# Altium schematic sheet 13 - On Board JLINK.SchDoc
size B; CompanyName: Microchip Technology Inc.; Organization: Microchip Technology; Address1: 2355 West Chandler Blvd.; Address2: Chandler, AZ  85224; Address4: USA; DocumentNumber: 13; SheetNumber: 13; SheetTotal: 13; SheetTitle: On Board JLINK
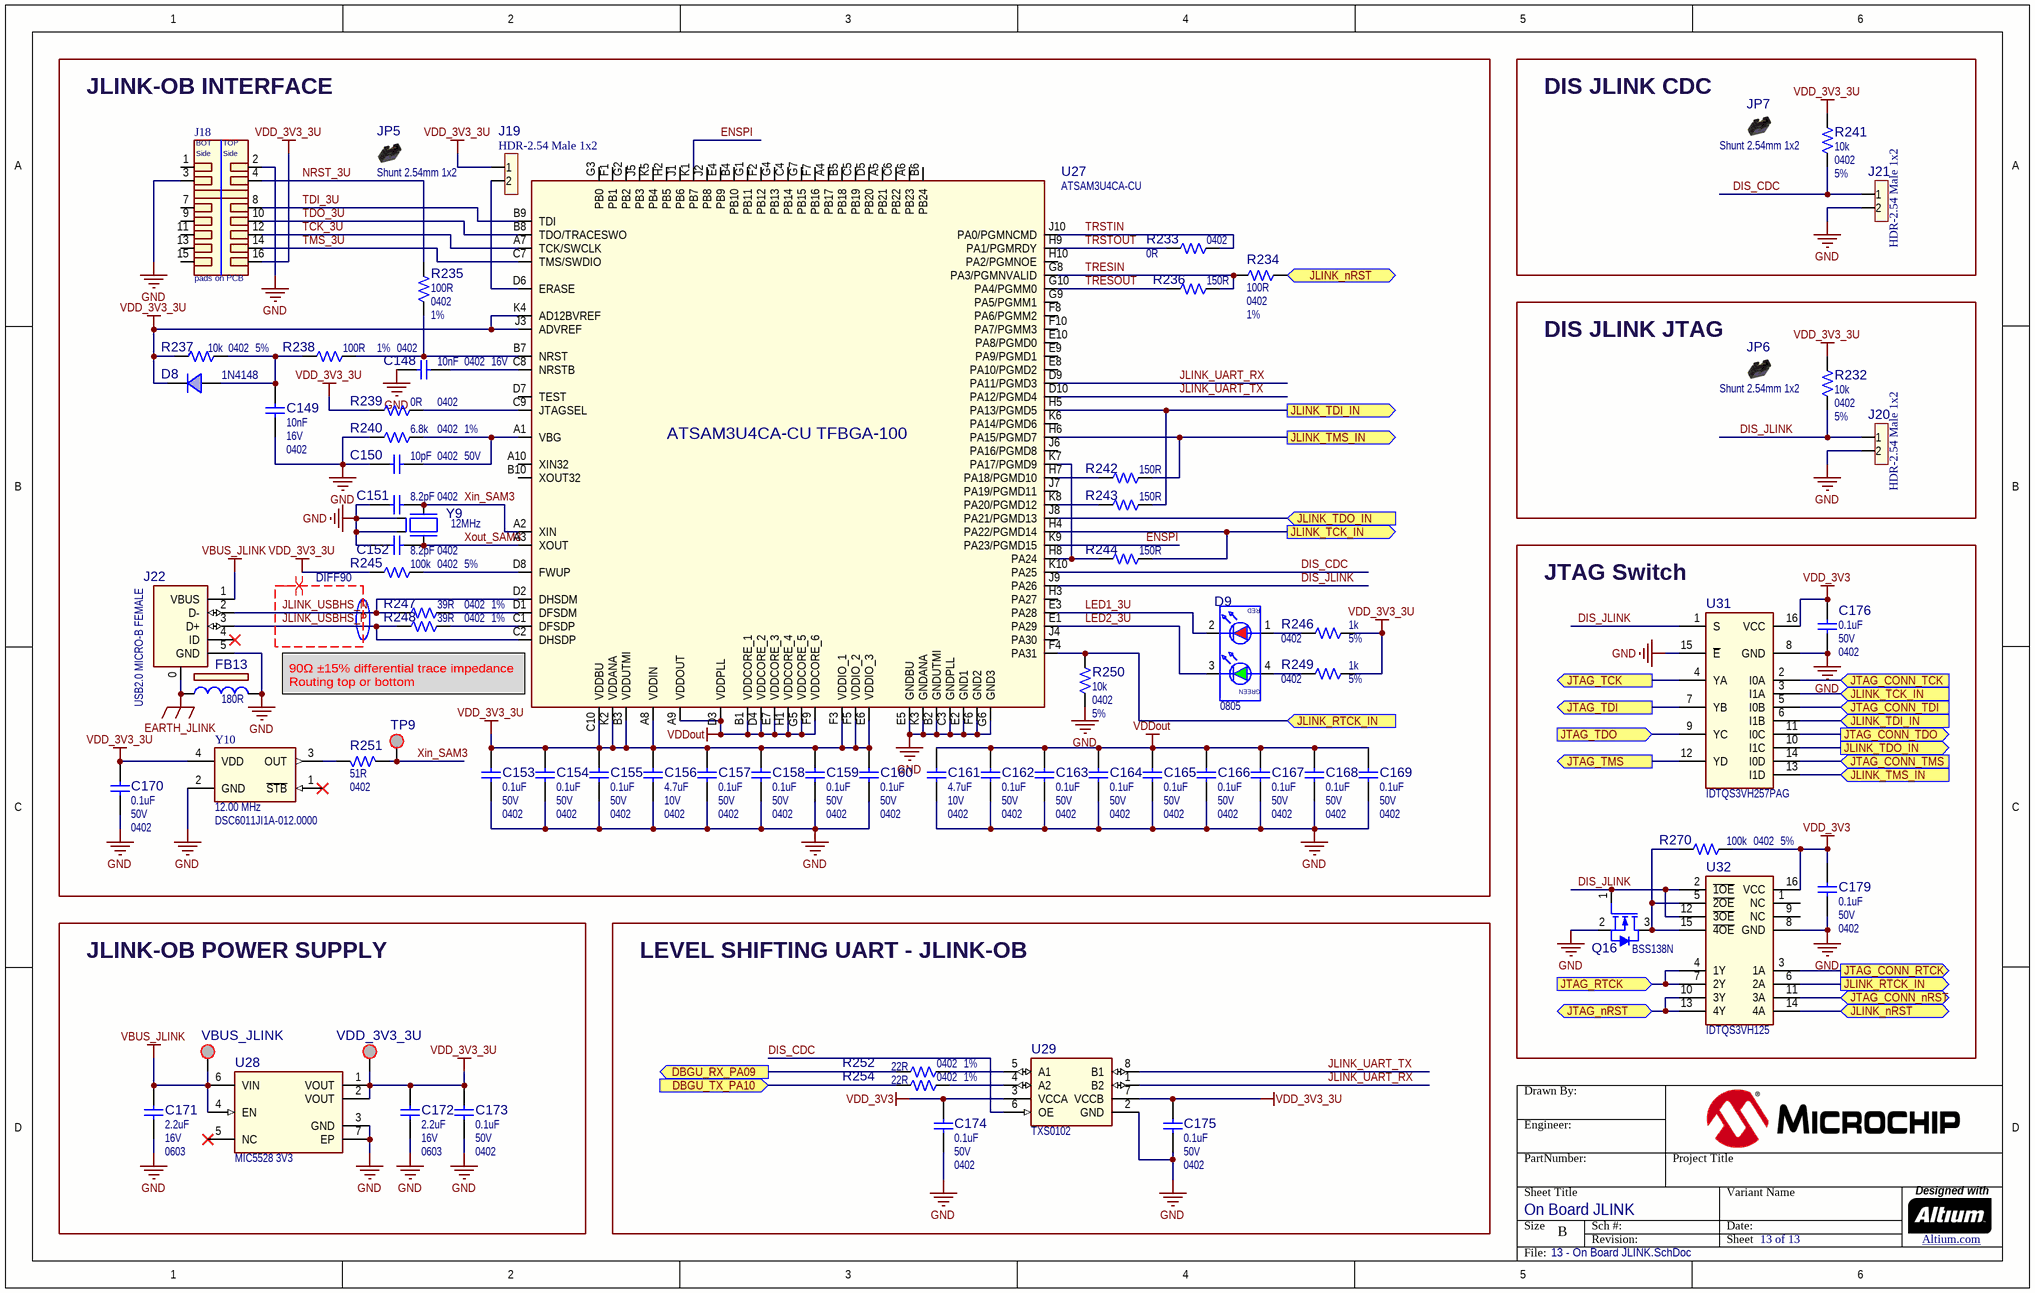
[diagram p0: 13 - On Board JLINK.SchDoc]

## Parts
?  (no value)  (graphical)
C148  value 10nF  Voltage: 16V  Package: 0402  [CAP_C_0402]  (hidden comment: Capacitor NP)
C149  value 10nF  Voltage: 16V  Package: 0402  [CAP_C_0402]  (hidden comment: Capacitor NP)
C150  value 10pF  Voltage: 50V  Package: 0402  [CAP_C_0402]  (hidden comment: Capacitor NP)
C151  value 8.2pF  Package: 0402  [CAP_C_0402]  (hidden comment: Capacitor NP)
C152  value 8.2pF  Package: 0402  [CAP_C_0402]  (hidden comment: Capacitor NP)
C153  value 0.1uF  Voltage: 50V  Package: 0402  [CAP_C_0402]  (hidden comment: Capacitor NP)
C154  value 0.1uF  Voltage: 50V  Package: 0402  [CAP_C_0402]  (hidden comment: Capacitor NP)
C155  value 0.1uF  Voltage: 50V  Package: 0402  [CAP_C_0402]  (hidden comment: Capacitor NP)
C156  value 4.7uF  Voltage: 10V  Package: 0402  [CAP_C_0402]  (hidden comment: Capacitor NP)
C157  value 0.1uF  Voltage: 50V  Package: 0402  [CAP_C_0402]  (hidden comment: Capacitor NP)
C158  value 0.1uF  Voltage: 50V  Package: 0402  [CAP_C_0402]  (hidden comment: Capacitor NP)
C159  value 0.1uF  Voltage: 50V  Package: 0402  [CAP_C_0402]  (hidden comment: Capacitor NP)
C160  value 0.1uF  Voltage: 50V  Package: 0402  [CAP_C_0402]  (hidden comment: Capacitor NP)
C161  value 4.7uF  Voltage: 10V  Package: 0402  [CAP_C_0402]  (hidden comment: Capacitor NP)
C162  value 0.1uF  Voltage: 50V  Package: 0402  [CAP_C_0402]  (hidden comment: Capacitor NP)
C163  value 0.1uF  Voltage: 50V  Package: 0402  [CAP_C_0402]  (hidden comment: Capacitor NP)
C164  value 0.1uF  Voltage: 50V  Package: 0402  [CAP_C_0402]  (hidden comment: Capacitor NP)
C165  value 0.1uF  Voltage: 50V  Package: 0402  [CAP_C_0402]  (hidden comment: Capacitor NP)
C166  value 0.1uF  Voltage: 50V  Package: 0402  [CAP_C_0402]  (hidden comment: Capacitor NP)
C167  value 0.1uF  Voltage: 50V  Package: 0402  [CAP_C_0402]  (hidden comment: Capacitor NP)
C168  value 0.1uF  Voltage: 50V  Package: 0402  [CAP_C_0402]  (hidden comment: Capacitor NP)
C169  value 0.1uF  Voltage: 50V  Package: 0402  [CAP_C_0402]  (hidden comment: Capacitor NP)
C170  value 0.1uF  Voltage: 50V  Package: 0402  [CAP_C_0402]  (hidden comment: Capacitor NP)
C171  value 2.2uF  Voltage: 16V  Package: 0603  [CAP_C_0603]  (hidden comment: Capacitor NP)
C172  value 2.2uF  Voltage: 16V  Package: 0603  [CAP_C_0603]  (hidden comment: Capacitor NP)
C173  value 0.1uF  Voltage: 50V  Package: 0402  [CAP_C_0402]  (hidden comment: Capacitor NP)
C174  value 0.1uF  Voltage: 50V  Package: 0402  [CAP_C_0402]  (hidden comment: Capacitor NP)
C175  value 0.1uF  Voltage: 50V  Package: 0402  [CAP_C_0402]  (hidden comment: Capacitor NP)
C176  value 0.1uF  Voltage: 50V  Package: 0402  [CAP_C_0402]  (hidden comment: Capacitor NP)
C179  value 0.1uF  Voltage: 50V  Package: 0402  [CAP_C_0402]  (hidden comment: Capacitor NP)
D8  value 1N4148  [SOD-323]  (hidden comment: Diode Single)
D9  Package: 0805  [LED_DUAL_SMD_2x1.25mm]  (hidden comment: LED DUAL 4 pin)
FB13  value 180R  [IND_C_0603]  (hidden comment: Ferrite Bead)
J18  pads on PCB  [CON_EDGE-CARD_PCB_RA_MEC1-108-02-F-D-RA1-SL]  (no BOM)
J19  value HDR-2.54 Male 1x2  [HDR_M_2.54_1x2]  (hidden comment: Header 1x2)
J20  value HDR-2.54 Male 1x2  [HDR_M_2.54_1x2]  (hidden comment: Header 1x2)
J21  value HDR-2.54 Male 1x2  [HDR_M_2.54_1x2]  (hidden comment: Header 1x2)
J22  value USB2.0 MICRO-B FEMALE  [CON_USB_Micro-AB_SMD_TH_RA_FCI_10118194-0001LF]  (hidden comment: CON USB2.0 Mini_Micro)
JP5  value Shunt 2.54mm 1x2  [Jumper_Mechanical]  (hidden comment: Jumper Mechanical)  (mechanical)
JP6  value Shunt 2.54mm 1x2  [Jumper_Mechanical]  (hidden comment: Jumper Mechanical)  (mechanical)
JP7  value Shunt 2.54mm 1x2  [Jumper_Mechanical]  (hidden comment: Jumper Mechanical)  (mechanical)
Q16  value BSS138N  [SOT-23-3]  (hidden comment: Transistor MOS-N GSD)
R232  value 10k  Package: 0402  Tolerance: 5%  [RES_C_0402]  (hidden comment: Resistor)
R233  value 0R  Package: 0402  [RES_C_0402]  (hidden comment: Resistor)
R234  value 100R  Package: 0402  Tolerance: 1%  [RES_C_0402]  (hidden comment: Resistor)
R235  value 100R  Package: 0402  Tolerance: 1%  [RES_C_0402]  (hidden comment: Resistor)
R236  value 150R  [RES_C_0402]  (hidden comment: Resistor)
R237  value 10k  Package: 0402  Tolerance: 5%  [RES_C_0402]  (hidden comment: Resistor)
R238  value 100R  Package: 0402  Tolerance: 1%  [RES_C_0402]  (hidden comment: Resistor)
R239  value 0R  Package: 0402  [RES_C_0402]  (hidden comment: Resistor)
R240  value 6.8k  Package: 0402  Tolerance: 1%  [RES_C_0402]  (hidden comment: Resistor)
R241  value 10k  Package: 0402  Tolerance: 5%  [RES_C_0402]  (hidden comment: Resistor)
R242  value 150R  [RES_C_0402]  (hidden comment: Resistor)
R243  value 150R  [RES_C_0402]  (hidden comment: Resistor)
R244  value 150R  [RES_C_0402]  (hidden comment: Resistor)
R245  value 100k  Package: 0402  Tolerance: 5%  [RES_C_0402]  (hidden comment: Resistor)
R246  value 1k  Package: 0402  Tolerance: 5%  [RES_C_0402]  (hidden comment: Resistor)
R247  value 39R  Package: 0402  Tolerance: 1%  [RES_C_0402]  (hidden comment: Resistor)
R248  value 39R  Package: 0402  Tolerance: 1%  [RES_C_0402]  (hidden comment: Resistor)
R249  value 1k  Package: 0402  Tolerance: 5%  [RES_C_0402]  (hidden comment: Resistor)
R250  value 10k  Package: 0402  Tolerance: 5%  [RES_C_0402]  (hidden comment: Resistor)
R251  value 51R  Package: 0402  [RES_C_0402]  (hidden comment: Resistor)
R252  value 22R  Package: 0402  Tolerance: 1%  [RES_C_0402]  (hidden comment: Resistor)
R254  value 22R  Package: 0402  Tolerance: 1%  [RES_C_0402]  (hidden comment: Resistor)
R270  value 100k  Package: 0402  Tolerance: 5%  [RES_C_0402]  (hidden comment: Resistor)
TP9  SMD Test Point  [TP_1x1_SMD]  (value not drawn)  (no BOM)
U27  ATSAM3U4CA-CU TFBGA-100  value ATSAM3U4CA-CU  [TFBGA-100_P0.8_9x9x1.1]
U28  value MIC5528 3V3  [DFN-6_1.2x1.2]  (hidden comment: MIC5528MT DFN-6)
U29  TXS0102  [US-8]
U31  value IDTQS3VH257PAG  [TSSOP-16]  (hidden comment: IDTQS3VH257 TSSOP-16)
U32  value IDTQS3VH125  [QSOP-16]  (hidden comment: IDTQS3VH125 SSOP-16)
VBUS_JLINK  SMD Test Point  [TP_1x1_SMD]  (value not drawn)  (no BOM)
VDD_3V3_3U  SMD Test Point  [TP_1x1_SMD]  (value not drawn)  (no BOM)
Y9  value 12MHz  [CRYSTAL_L7.5W5.2H1.4]  (hidden comment: Crystal 4 Pins)
Y10  value 12.00 MHz  Manufacturer Part Number 1: DSC6011JI1A-012.0000  [OSCILLATOR_DSC60000L2.5W2.0H0.89]  (hidden comment: OSCILLATOR DSC60XX)

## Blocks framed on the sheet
JLINK-OB INTERFACE: C148-C170 D8 D9 FB13 J18 J19 J22 JP5 R233-R240 R242-R251 TP9 U27 Y9 Y10
DIS JLINK CDC: J21 JP7 R241
DIS JLINK JTAG: J20 JP6 R232
JTAG Switch: C176 C179 Q16 R270 U31 U32
JLINK-OB POWER SUPPLY: C171-C173 U28 VBUS_JLINK VDD_3V3_3U
LEVEL SHIFTING UART - JLINK-OB: C174 C175 R252 R254 U29

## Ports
DBGU_RX_PA09 (out), DBGU_TX_PA10 (in), JLINK_nRST (bidir), JLINK_RTCK_IN (in), JLINK_RTCK_IN (out), JLINK_TCK_IN (in), JLINK_TCK_IN (out), JLINK_TDI_IN (in), JLINK_TDI_IN (out), JLINK_TDO_IN (in), JLINK_TDO_IN (out), JLINK_TMS_IN (in), JLINK_TMS_IN (out), JTAG_CONN_nRST (bidir), JTAG_CONN_RTCK (out), JTAG_CONN_TCK (in), JTAG_CONN_TDI (in), JTAG_CONN_TDO (out), JTAG_CONN_TMS (in), JTAG_nRST (bidir), JTAG_RTCK (in), JTAG_TCK (out), JTAG_TDI (out), JTAG_TDO (in), JTAG_TMS (out)

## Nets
EARTH_JLINK: FB13.1 J22.0(SHLD)
GND: C148.1 C149.1 C150.2 C151.2 C152.2 C153.2 C154.1 C155.2 C156.1 C157.1 C158.1 C159.1 C160.1 C161.1 C162.1 C163.2 C164.2 C165.2 C166.2 C167.2 C168.2 C169.1 C170.1 C171.2 C172.1 C173.1 C174.1 C175.1 C176.2 C179.2 FB13.2 J18.2 J18.3 J20.2 J21.2 J22.5(GND) Q16.2(S) R240.1 R250.2 U27.B2(GNDUTMI) U27.C3(GNDPLL) U27.E2(GND1) U27.E5(GNDBU) U27.F6(GND2) U27.G6(GND3) U27.K3(GNDANA) U28.3(GND) U28.7(EP) U29.2(GND) U31.8(GND) U31.15(~{E}) U32.8(GND) Y9.2(GND) Y9.4(GND) Y10.2(GND)
VBUS_JLINK: C171.1 J22.1(VBUS) U28.4(EN) U28.6(VIN) VBUS_JLINK.1
VDD_3V3: C174.2 C176.1 C179.1 R270.1 U29.3(VCCA) U31.16(VCC) U32.16(VCC)
VDD_3V3_3U: C153.1 C154.2 C155.1 C156.2 C157.2 C158.2 C159.2 C160.2 C170.2 C172.2 C173.2 C175.2 D8.2(K) J18.16 J19.1 R232.1 R237.1 R239.1 R241.1 R245.1 R246.1 R249.1 U27.A8(VDDIN) U27.B3(VDDUTMI) U27.C10(VDDBU) U27.E6(VDDIO_3) U27.F3(VDDIO_1) U27.F5(VDDIO_2) U27.J3(ADVREF) U27.K2(VDDANA) U27.K4(AD12BVREF) U28.1(VOUT) U28.2(VOUT) U29.7(VCCB) VDD_3V3_3U.1 Y10.4(VDD)
VDDout: C161.2 C162.2 C163.1 C164.1 C165.1 C166.1 C167.1 C168.1 C169.2 U27.A9(VDDOUT) U27.B1(VDDCORE_1) U27.D3(VDDPLL) U27.D4(VDDCORE_2) U27.E7(VDDCORE_3) U27.F9(VDDCORE_6) U27.G5(VDDCORE_5) U27.H1(VDDCORE_4)
DBGU_RX_PA09: R252.1 ; port DBGU_RX_PA09
DBGU_TX_PA10: R254.1 ; port DBGU_TX_PA10
DIS_CDC: J21.1 R241.2 U27.K10(PA25) U29.6(OE)
DIS_JLINK: J20.1 Q16.1(G) R232.2 U27.J9(PA26) U31.1(S) U32.2(~{1OE}) U32.12(~{3OE})
ENSPI: U27.K1(PB7) U27.K9(PA23/PGMD15)
JLINK_nRST: R234.2 U32.14(4A) ; port JLINK_nRST
JLINK_RTCK_IN: R250.1 U27.F4(PA31) U32.6(2A) ; port JLINK_RTCK_IN
JLINK_TCK_IN: R244.2 U27.H4(PA22/PGMD14) U31.3(I1A) ; port JLINK_TCK_IN
JLINK_TDI_IN: R243.2 U27.H5(PA13/PGMD5) U31.6(I1B) ; port JLINK_TDI_IN
JLINK_TDO_IN: U27.J8(PA21/PGMD13) U31.10(I1C) ; port JLINK_TDO_IN
JLINK_TMS_IN: R242.2 U27.H6(PA15/PGMD7) U31.13(I1D) ; port JLINK_TMS_IN
JLINK_UART_RX: U27.D9(PA11/PGMD3) U29.1(B2)
JLINK_UART_TX: U27.D10(PA12/PGMD4) U29.8(B1)
JLINK_USBHS_N: J22.2(D-) R247.1 U27.D2(DHSDM)
JLINK_USBHS_P: J22.3(D+) R248.1 U27.C2(DHSDP)
JTAG_CONN_nRST: U32.11(3A) ; port JTAG_CONN_nRST
JTAG_CONN_RTCK: U32.3(1A) ; port JTAG_CONN_RTCK
JTAG_CONN_TCK: U31.2(I0A) ; port JTAG_CONN_TCK
JTAG_CONN_TDI: U31.5(I0B) ; port JTAG_CONN_TDI
JTAG_CONN_TDO: U31.11(I0C) ; port JTAG_CONN_TDO
JTAG_CONN_TMS: U31.14(I0D) ; port JTAG_CONN_TMS
JTAG_nRST: U32.10(3Y) U32.13(4Y) ; port JTAG_nRST
JTAG_RTCK: U32.4(1Y) U32.7(2Y) ; port JTAG_RTCK
JTAG_TCK: U31.4(YA) ; port JTAG_TCK
JTAG_TDI: U31.7(YB) ; port JTAG_TDI
JTAG_TDO: U31.9(YC) ; port JTAG_TDO
JTAG_TMS: U31.12(YD) ; port JTAG_TMS
LED1_3U: D9.2(K1) U27.E3(PA28)
LED2_3U: D9.3(K2) U27.E1(PA29)
NRST_3U: J18.4 R235.2
TCK_3U: J18.12 U27.A7(TCK/SWCLK)
TDI_3U: J18.8 U27.B9(TDI)
TDO_3U: J18.10 U27.B8(TDO/TRACESWO)
TMS_3U: J18.14 U27.C7(TMS/SWDIO)
TRESIN: R234.1 R236.2 U27.G8(PA3/PGMNVALID)
TRESOUT: R236.1 U27.G10(PA4/PGMM0)
TRSTIN: R233.2 U27.J10(PA0/PGMNCMD)
TRSTOUT: R233.1 U27.H9(PA1/PGMRDY)
Xin_SAM3: C151.1 R251.2 TP9.1 U27.A2(XIN) Y9.1(Osc1)
Xout_SAM3: C152.1 U27.A3(XOUT) Y9.3(Osc2)
NetC148_2: C148.2 U27.C8(NRSTB)
NetC149_2: C149.2 D8.1(A) R237.2 R238.1
NetC150_1: C150.1 R240.2 U27.A1(VBG)
NetD9_1: D9.1(A1) R246.2
NetD9_4: D9.4(A2) R249.2
NetJ19_2: J19.2 U27.D6(ERASE)
NetQ16_3: Q16.3(D) R270.2 U32.5(~{2OE}) U32.15(~{4OE})
NetR235_1: R235.1 R238.2 U27.B7(NRST)
NetR239_2: R239.2 U27.C9(JTAGSEL)
NetR242_1: R242.1 U27.H7(PA18/PGMD10)
NetR243_1: R243.1 U27.K8(PA20/PGMD12)
NetR244_1: R244.1 U27.H8(PA24) U27.K7(PA17/PGMD9)
NetR245_2: R245.2 U27.D8(FWUP)
NetR247_2: R247.2 U27.D1(DFSDM)
NetR248_2: R248.2 U27.C1(DFSDP)
NetR251_1: R251.1 Y10.3(OUT)
NetR252_2: R252.2 U29.5(A1)
NetR254_2: R254.2 U29.4(A2)

Not connected (* = marked no-connect by the designer): J18 1 7 9 11 13 15; J22 4(ID)*; U27 A4(PB17) A5(PB21) A6(PB23) A10(XIN32) B4(PB10) B5(PB18) B6(PB24) B10(XOUT32) C4(PB14) C5(PB19) C6(PB22) D5(PB20) D7(TEST) E4(PB9) E8(PA10/PGMD2) E9(PA9/PGMD1) E10(PA8/PGMD0) F1(PB1) F2(PB12) F7(PB16) F8(PA6/PGMM2) F10(PA7/PGMM3) G1(PB11) G2(PB2) G3(PB0) G4(PB13) G7(PB15) G9(PA5/PGMM1) H2(PB5) H3(PA27) H10(PA2/PGMNOE) J1(PB6) J2(PB8) J4(PA30) J5(PB3) J6(PA16/PGMD8) J7(PA19/PGMD11) K5(PB4) K6(PA14/PGMD6); U28 5(NC)*; U32 1(NC) 9(NC); Y10 1(~{STB})*

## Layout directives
differential pair; differential pair class DIFF90; net class DIFF90; rule Matched Net Lengths [Tolerance = 10mil]: JLINK_USBHS_N, JLINK_USBHS_P

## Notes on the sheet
- (near U27) 90Ω ±15% differential trace impedance
  Routing top or bottom

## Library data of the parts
? = Title Block B
C148 C149 = CAP0278: Capacitor; Manufacturer 1: KEMET; Manufacturer Part Number 1: C0402C103K4RACTU; Description_: CAP CER 10000pF 16V 10% X7R SMD 0402; Dev Tools Status: Production; Tolerance: 10%; Temperature Coeffcient: X7R; Type: Ceramic; Populated: YES
C150 = CAP0613: Capacitor; Manufacturer 1: Murata; Manufacturer Part Number 1: GRM1555C1H100JZ01D; Description_: CAP CER 10pF 50V 5% NP0 SMD 0402; Dev Tools Status: Production; Tolerance: 5%; Temperature Coeffcient: NP0; Type: Ceramic; Populated: Yes
C151 C152 = CAP1379: Capacitor; Manufacturer 1: Johanson Technology Inc; Manufacturer Part Number 1: 500R07S8R2CV4T; Voltage: 50V; Description_: CAP HiQ 8.2pF 50V 0.25pF NP0 3.04GHz SMD 0402; Dev Tools Status: Production; Tolerance: 0.25pF; Temperature Coeffcient: NP0; ESR: 0.04R; Type: HiQ; Owner: Gabor Bihari; Populated: DNP
C153-C155 C157-C160 C162-C170 C173-C176 C179 = CAP1463: Capacitor; Manufacturer 1: TDK Corporation; Manufacturer Part Number 1: C1005X7R1H104K050BB; Description_: CAP CER 0.1uF 50V 10% X7R SMD 0402; Dev Tools Status: Production; Tolerance: 10%; Temperature Coeffcient: X7R; Type: Ceramic; Owner: Jamus Griego; Populated: YES
C156 C161 = CAP1684: Capacitor; Manufacturer 1: TDK Corporation; Manufacturer Part Number 1: C1005X5R1A475K050BC; Description_: CAP CER 4.7uF 10V 10% X5R SMD 0402; Dev Tools Status: Design; Tolerance: 10%; Temperature Coeffcient: X5R; Type: Ceramic; Owner: Jesus Aviles; Populated: YES
C171 C172 = CAP0597: Capacitor; Manufacturer 1: TDK; Manufacturer Part Number 1: C1608X5R1C225K; Description_: CAP CER 2.2uF 16V 10% X5R SMD 0603; Dev Tools Status: Production; Tolerance: 10%; Temperature Coeffcient: X5R; Type: Ceramic; Populated: Yes
D8 = DIODE0096: Manufacturer 1: Diodes Incorporated; Manufacturer Part Number 1: 1N4148WS-7-F; Description_: DIO RECT 1N4148WS 1.25V 150mA 75V SOD-323; Dev Tools Status: Production; Type: Rectifier Single; Forward Current: 150mA; Power: 200mW; Reverse Current: 50uA; Reverse Voltage: 75V; Populated: YES
D9 = DIODE1110: LED; Manufacturer 1: Kingbright Corp; Manufacturer Part Number 1: APHBM2012SURKCGKC; Value: RED, GREEN; Description_: DIO LED BI RED, GREEN 1.95V, 2.1V 30mA 0805; Dev Tools Status: Production; Type: LED Bicolor; Forward Current: 30mA; Power: 75mW; Reverse Current: 10uA; Owner: Bogdan P (M91398); Populated: Yes
FB13 = IND1453: FERRITE 180R 1.5A SMD 0603; Manufacturer 1: Murata Electronics North America; Manufacturer Part Number 1: BLM18PG181SN1D; Dev Tools Status: Design; Owner: Dragos Danaila; DCR: 0.09R; Test Frequency: 100MHz; Populated: YES
J18 = CON1674: CON_PCB_MEC1-108-02-F-D-RA1-SL; Manufacturer 1: Samtec Inc.; Description_: CON EDGE MEC1 1mm 14P Male PCB VERT; Dev Tools Status: Design; Owner: Dragos Danaila; Current: 1.6A; Populated: NO
J19 = CON1312: Manufacturer 1: Sullins Connector Solutions; Manufacturer Part Number 1: PREC002SAAN-RC; Description_: CON HDR-2.54 Male 1x2 Tin 5.84MH TH VERT; Dev Tools Status: Production; Owner: Randolph Sobrepena; Populated: DNP
J20 J21 = CON1312: Manufacturer 1: Sullins Connector Solutions; Manufacturer Part Number 1: PREC002SAAN-RC; Description_: CON HDR-2.54 Male 1x2 Tin 5.84MH TH VERT; Dev Tools Status: Production; Owner: Randolph Sobrepena; Populated: YES
J22 = CON1383: Connector USB Mini; Manufacturer 1: FCI; Manufacturer Part Number 1: 10118194-0001LF; Description_: CON USB2.0 MICRO-B FEMALE TH/SMD R/A; Dev Tools Status: Production; Owner: Jamus Griego; Populated: YES
JP5 = HW1006: Manufacturer 1: 3M; Manufacturer Part Number 1: 969102-0000-DA; MCHP-ID: HW1006; Description_: MECH HW JUMPER 2.54mm 1x2; Dev Tools Status: Production; Owner: Mike Ragsdale; Populated: DNP
JP6 JP7 = HW1006: Manufacturer 1: 3M; Manufacturer Part Number 1: 969102-0000-DA; MCHP-ID: HW1006; Description_: MECH HW JUMPER 2.54mm 1x2; Dev Tools Status: Production; Owner: Mike Ragsdale; Populated: MECH
Q16 = TRA1223: Transistor MOS; Manufacturer 1: Infineon Technologies; Manufacturer Part Number 1: BSS138NH6327XTSA2; Description_: TRANS FET N-CH BSS138N 60V 230mA SOT23-3; Dev Tools Status: Production; Type: FET; Current: 230mA; Drain to Source Voltage: 60V; Gate to Source Voltage: 20V; Power: 0.36W; Owner: Dragos Danaila; Populated: YES
R232 R237 R241 R250 = RSMT0439: Manufacturer 1: Vishay; Manufacturer Part Number 1: CRCW040210K0JNED; Description_: RES TKF 10k 5% 1/16W SMD 0402; Dev Tools Status: Production; Voltage: 50V; Temperature Coeffcient: 100ppm/C; Power: 1/16W; Populated: Yes
R233 = RSMT1040: Manufacturer 1: Yageo; Manufacturer Part Number 1: RC0402JR-070RL; Description_: RES TKF 0R 1/16W SMD 0402; Dev Tools Status: Production; Power: 1/16W; Owner: Sompoch Loboonlert; Populated: Yes
R234 R235 R238 = RES1587: Manufacturer 1: Yageo; Manufacturer Part Number 1: RC0402FR-07100RL; Description_: RES TKF 100R 1% 1/16W SMD 0402; Dev Tools Status: Design; Voltage: 50V; Temperature Coeffcient: 100ppm/C; Power: 1/16W; Owner: Sorin Stanoaia; Populated: YES
R236 R242-R244 = RSMT1167: Manufacturer 1: Vishay Dale; Manufacturer Part Number 1: CRCW0402150RFKED; Description_: RES TKF 150R 1% 1/16W MF 0402; Dev Tools Status: Production; Owner: Jamus Griego; Populated: YES
R239 = RSMT1040: Manufacturer 1: Yageo; Manufacturer Part Number 1: RC0402JR-070RL; Description_: RES TKF 0R 1/16W SMD 0402; Dev Tools Status: Production; Power: 1/16W; Owner: Sompoch Loboonlert; Populated: DNP
R240 = RSMT1211: Manufacturer 1: Vishay Dale; Manufacturer Part Number 1: CRCW04026K80FKED; Description_: RES TKF 6.8k 1% 1/16W SMD 0402; Dev Tools Status: Design; Voltage: 50V; Temperature Coeffcient: 100ppm/C; Power: 1/16W; Owner: Dragos Danaila; Populated: YES
R245 R270 = RES2196: Manufacturer 1: Yageo; Manufacturer Part Number 1: RC0402JR-07100KL; Description_: RES TKF 100k 5% 1/16W SMD 0402; Dev Tools Status: Design; Temperature Coeffcient: 100ppm/C; Power: 1/16W; Owner: Ilie Galan; Populated: YES
R246 R249 = RSMT0316: Manufacturer 1: Panasonic; Manufacturer Part Number 1: ERJ-2GEJ102X; Description_: RES TKF 1k 5% 1/16W SMD 0402; Dev Tools Status: Production; Voltage: 50V; Temperature Coeffcient: 200ppm/C; Power: 1/16W; Owner: Tad Ahlvers; Populated: YES
R247 R248 = RES1800: Manufacturer 1: Yageo; Manufacturer Part Number 1: RC0402FR-0739RL; Description_: RES TKF 39R 1% 1/16W SMD 0402; Dev Tools Status: Design; Circuit Type: Single; Power: 1/16W; Owner: Sompoch Loboonlert; Populated: YES
R251 = RSMT1243: Manufacturer 1: Yageo; Manufacturer Part Number 1: RC0402FR-0751RL; Tolerance: 1%; Description_: RES TKF 51R 1% 1/16W SMD 0402; Dev Tools Status: Design; Voltage: 100V; Temperature Coeffcient: 100ppm/C; Current: 1A; Power: 1/16W; Owner: Ciprian Abramov; Populated: YES
R252 R254 = RES1474: Manufacturer 1: Panasonic Electronic Components; Manufacturer Part Number 1: ERJ-2RKF22R0X; Description_: RES TKF 22R 1% 1/20W SMD 0402; Dev Tools Status: Production; Temperature Coeffcient: 100ppm/C; Circuit Type: Isolated; Power: 1/10W; Owner: Mike Ragsdale; Populated: YES
TP9 VBUS_JLINK VDD_3V3_3U = TEST-POINT: Test Point pad 1.00mm
U27 = MIC7470: Manufacturer 1: Microchip Technology; Description_: MCHP MCU 32-BIT 96MHz 256kB 56kB ATSAM3U4CA-CU 100BGA; MAPS Description: TFBGA,GREEN,IND TEMP,MRL A; Dev Tools Status: Design; Owner: Dragos Danaila; MPC: 58Z247A2BC02; LeadContent: Pb-FREE; TempRange: -40C to +85C; Stage: REL; PackageWidth: 9x9x1.2mm; PackingMedia: TRAY; ForceMinOrderQtyMult: True; MinOrderQty: 260; LeadCount: 100; Program Memory KBytes: 256; Program Memory KWords: 64; Ram: 51200; EEPROM: 0; IOPins: 57; MaxSpeed: 96; OscillatorMHz: 4,8,12Mhz,32Khz; ADC Channels: 8; ADCBit: 12; USART: 4; I2C: 1; Input Capture: 6; CapTouchCH: 28; DigitalTimerQty_16bit: 3; Populated: YES
U28 = MIC6905: Manufacturer 1: Microchip Technology; Manufacturer Part Number 1: MIC5528-3.3YMT-TR; Description_: MCHP ANALOG LDO 3.3V MIC5528-3.3YMT-TR 6-TDFN; MAPS Description: Single, 500mA LDO w/ Auto Discharge & Internal Enable Pulldown; Dev Tools Status: Production; Owner: Tim Moffat; MPC: TKFC1YHHAA02; LeadContent: Pb-FREE; PackingMedia: T/R; Stage: REL; LeadCount: 6; PackageWidth: 1.2x1.2x0.6mm; ForceMinOrderQtyMult: True; MinOrderQty: 1; TempRange: -40C to +125C; tblDeviceFamilyID: 7519; Populated: YES
U29 = IC1128: Level Shifter; Manufacturer 1: Texas Instruments; Manufacturer Part Number 1: TXS0102DCUR; MCHP-ID: IC1128; Description_: IC TRANSCEIVER TXS0102 US-8; Dev Tools Status: Production; Owner: Bogdan P (M91398); Populated: Yes
U31 = IC1517: Manufacturer 1: IDT, Integrated Device Technology Inc; Manufacturer Part Number 1: QS3VH257PAG; MCHP-ID: IC1517; Description_: IC SWITCHER  MUX/DEMUX IDTQS3VH257 QUAD 2:1 TSSOP-16; Dev Tools Status: Design; Owner: Ilie Galan; Populated: YES
U32 = IC1516: Manufacturer 1: IDT, Integrated Device Technology Inc; Manufacturer Part Number 1: QS3VH125QG; MCHP-ID: IC1516; Description_: IC SWITCHER IDTQS3VH125 Bus Switch 1 x 4:1 QSOP-16; Dev Tools Status: Design; Owner: Ilie Galan; Populated: YES
Y9 = OSC1155: Crystal; Manufacturer 1: IQD Frequency Products; Manufacturer Part Number 1: LFXTAL026384Reel; Description_: CRYSTAL 12MHz 16pF SMD L7.5W5.0H1.4; Dev Tools Status: Design; Owner: Dragos Danaila; Tolerance: 30ppm; Load Capacitance: 16pF; Populated: DNP
Y10 = MIC7210: Manufacturer 1: Microchip Technology Inc; Description_: MCHP CLOCK OSCILLATOR SINGLE 12.000MHZ DSC6011JI1A-012.0000 VLGA; Dev Tools Status: Production; Owner: Tim Moffat; Populated: YES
